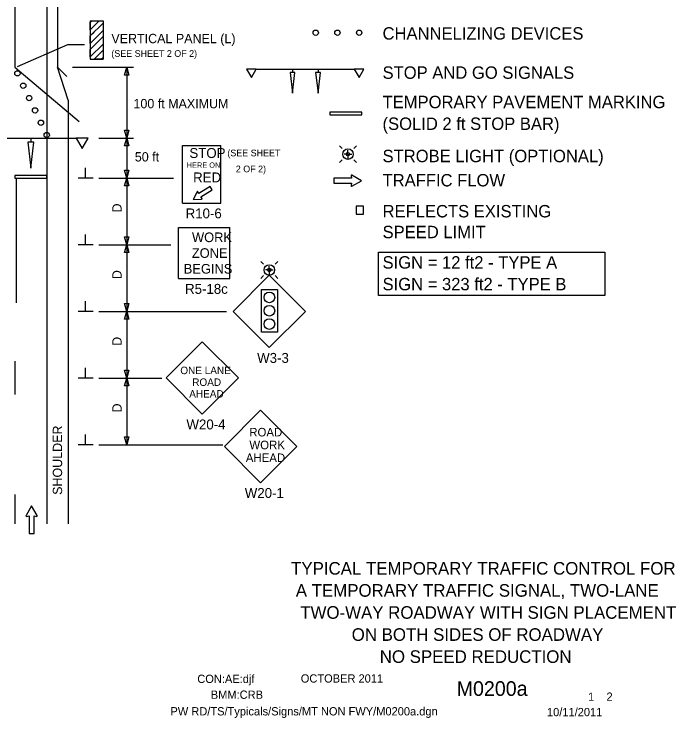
# Model space of a CAD drawing. Extents: x 16520 to 18479, y 5662 to 6927.
# Drawn here: x 16953 to 17450, y 5932 to 6460 of the extents above; entities that cross this region are included whole.
import ezdxf

# ---------------------------------------------------------------- set-up
doc = ezdxf.new("R2010")
doc.units = 0
for name, color, linetype in [('ALI_LEGAL_EX', 7, 'Continuous'), ('BORDER', 7, 'Continuous'), ('BORDER_SIGNAL_WO', 7, 'Continuous'), ('MT_SCRATCH_LEVEL_E', 7, 'Continuous'), ('PAVT_EDGE_EX', 7, 'Continuous'), ('TRAFFIC_SIGNS_PR', 7, 'Continuous'), ('TYPICAL_TEXT_DIMEN_EX', 7, 'Continuous'), ('TYPICAL_TEXT_DIMEN_PR', 7, 'Continuous')]:
    doc.layers.add(name, color=color, linetype=linetype)

msp = doc.modelspace()

# ---------------------------------------------------------------- linework, layer by layer
at = {"layer": 'ALI_LEGAL_EX'}
for points in [[(16954.78, 6336.76), (16954.78, 6243.13)], [(16953.78, 6199.43), (16953.78, 6174.43)], [(16953.78, 6099.43), (16953.78, 6077.5)]]:
    msp.add_lwpolyline(points, dxfattribs=at)
at = {"layer": 'MT_SCRATCH_LEVEL_E'}
for p, q in [((17206.32, 6336.64), (17193.07, 6336.64)), ((17193.07, 6336.64), (17193.07, 6332.9)), ((17206.32, 6336.64), (17193.07, 6336.64)), ((17193.07, 6336.64), (17193.07, 6332.9)), ((17206.01, 6338.42), (17206.32, 6336.64)), ((17206.01, 6338.42), (17206.32, 6336.64)), ((17213.93, 6334.79), (17206.69, 6338.9)), ((17213.93, 6334.79), (17206.69, 6338.9)), ((17193.07, 6332.9), (17206.32, 6332.9)), ((17193.07, 6332.9), (17206.32, 6332.9)), ((17206.32, 6332.9), (17206.01, 6331.12)), ((17206.32, 6332.9), (17206.01, 6331.12)), ((17206.69, 6330.64), (17213.93, 6334.79)), ((17206.69, 6330.64), (17213.93, 6334.79)), ((16966.37, 6090.97), (16962.26, 6083.73)), ((16966.37, 6090.97), (16962.26, 6083.73)), ((16970.52, 6083.73), (16966.37, 6090.97)), ((16970.52, 6083.73), (16966.37, 6090.97)), ((16962.74, 6083.04), (16964.52, 6083.36)), ((16962.74, 6083.04), (16964.52, 6083.36)), ((16964.52, 6083.36), (16964.52, 6070.1)), ((16964.52, 6083.36), (16964.52, 6070.1)), ((16968.26, 6070.1), (16968.26, 6083.36)), ((16968.26, 6083.36), (16970.04, 6083.04)), ((16968.26, 6070.1), (16968.26, 6083.36)), ((16968.26, 6083.36), (16970.04, 6083.04)), ((16964.52, 6070.1), (16968.26, 6070.1)), ((16964.52, 6070.1), (16968.26, 6070.1))]:
    msp.add_line(p, q, dxfattribs=at)
for centre, start, end in [((17206.47, 6338.49), 60.4248, 189.9638), ((17206.47, 6338.49), 60.4248, 189.9638), ((17206.47, 6331.05), 170.0362, 299.7731), ((17206.47, 6331.05), 170.0362, 299.7731), ((16962.67, 6083.5), 150.4248, 279.9638), ((16962.67, 6083.5), 150.4248, 279.9638), ((16970.11, 6083.5), 260.0362, 29.7731), ((16970.11, 6083.5), 260.0362, 29.7731)]:
    msp.add_arc(centre, 0.463, start, end, dxfattribs=at)
at = {"layer": 'PAVT_EDGE_EX'}
for p, q in [((16977.78, 6899.43), (16977.78, 6077.5)), ((16953.78, 6551.35), (16953.78, 6419.96)), ((16985.78, 6551.35), (16985.78, 6419.96)), ((16953.78, 6419.96), (17002.19, 6379.34)), ((16985.78, 6419.96), (16992.85, 6412.89)), ((16993.78, 6395.26), (16985.78, 6419.96)), ((16993.78, 6395.26), (16993.78, 6077.5))]:
    msp.add_line(p, q, dxfattribs=at)
at = {"layer": 'TRAFFIC_SIGNS_PR'}
for p, q in [((17010.4, 6454.77), (17020, 6454.77)), ((17010.4, 6454.77), (17010.4, 6425.97)), ((17010.4, 6453.68), (17011.49, 6454.77)), ((17010.4, 6448.02), (17017.15, 6454.77)), ((17010.4, 6454.77), (17020, 6454.77)), ((17010.4, 6454.77), (17010.4, 6425.97)), ((17010.4, 6453.68), (17011.49, 6454.77)), ((17010.4, 6448.02), (17017.15, 6454.77)), ((17010.4, 6443.5), (17020, 6453.1)), ((17010.4, 6443.5), (17020, 6453.1)), ((17020, 6454.77), (17020, 6425.97)), ((17020, 6454.77), (17020, 6425.97)), ((17010.4, 6437.84), (17020, 6447.44)), ((17010.4, 6437.84), (17020, 6447.44)), ((17010.4, 6433.32), (17020, 6442.92)), ((17010.4, 6433.32), (17020, 6442.92)), ((17011.81, 6444.91), (17013.23, 6446.33)), ((17011.81, 6444.91), (17013.23, 6446.33)), ((17010.4, 6427.66), (17020, 6437.26)), ((17010.4, 6427.66), (17020, 6437.26)), ((17013.24, 6425.97), (17020, 6432.73)), ((17013.24, 6425.97), (17020, 6432.73)), ((17010.4, 6425.97), (17020, 6425.97)), ((17010.4, 6425.97), (17020, 6425.97)), ((17018.89, 6425.97), (17020, 6427.08)), ((17018.89, 6425.97), (17020, 6427.08)), ((17134.84, 6418.4), (17208.44, 6418.4)), ((17162.04, 6418.4), (17162.04, 6415.98)), ((17181.24, 6418.4), (17181.24, 6415.98)), ((16907.78, 6366.76), (16999.78, 6366.76)), ((16965.78, 6366.76), (16965.78, 6363.74)), ((17079.55, 6361.23), (17108.35, 6361.23)), ((17079.55, 6318.03), (17079.55, 6361.23)), ((17093.95, 6361.23), (17093.95, 6361.23)), ((17108.35, 6318.03), (17108.35, 6361.23)), ((17199.4, 6359.04), (17197.37, 6361.07)), ((17203.68, 6354.76), (17203.68, 6357.63)), ((17207.96, 6359.04), (17209.99, 6361.07)), ((17203.68, 6354.76), (17200.8, 6354.76)), ((17203.68, 6354.76), (17203.68, 6350.82)), ((17203.68, 6354.76), (17206.56, 6354.76)), ((17199.4, 6350.47), (17197.37, 6348.44)), ((17209.99, 6348.44), (17207.96, 6350.47)), ((17079.55, 6318.03), (17108.35, 6318.03)), ((17076.71, 6261.4), (17076.71, 6299.8)), ((17076.71, 6299.8), (17115.11, 6299.8)), ((17115.11, 6261.4), (17115.11, 6299.8)), ((17140.42, 6272.16), (17138.39, 6274.19)), ((17148.98, 6272.16), (17151.01, 6274.19)), ((17144.7, 6267.88), (17141.82, 6267.88)), ((17144.7, 6267.88), (17144.7, 6270.76)), ((17144.7, 6267.88), (17144.7, 6263.94)), ((17144.7, 6267.88), (17147.58, 6267.88)), ((17144.7, 6263.94), (17117.55, 6236.79)), ((17140.42, 6263.6), (17138.39, 6261.56)), ((17171.85, 6236.79), (17144.7, 6263.94)), ((17151.01, 6261.56), (17148.98, 6263.6)), ((17076.71, 6261.4), (17115.11, 6261.4)), ((17117.55, 6236.79), (17144.7, 6209.63)), ((17144.7, 6209.63), (17171.85, 6236.79)), ((17094.37, 6214.01), (17067.22, 6186.86)), ((17121.52, 6186.86), (17094.37, 6214.01)), ((17067.22, 6186.86), (17094.37, 6159.71)), ((17094.37, 6159.71), (17121.52, 6186.86)), ((17138.12, 6162.62), (17110.97, 6135.46)), ((17165.27, 6135.46), (17138.12, 6162.62)), ((17110.97, 6135.46), (17138.12, 6108.31)), ((17138.12, 6108.31), (17165.27, 6135.46))]:
    msp.add_line(p, q, dxfattribs=at)
for points in [[(17011.49, 6454.77), (17017.15, 6454.77), (17010.4, 6448.02), (17010.4, 6453.68)], [(17011.49, 6454.77), (17017.15, 6454.77), (17010.4, 6448.02), (17010.4, 6453.68)], [(17010.4, 6443.5), (17020, 6453.1), (17020, 6447.44), (17010.4, 6437.84)], [(17010.4, 6443.5), (17020, 6453.1), (17020, 6447.44), (17010.4, 6437.84)], [(17010.4, 6433.32), (17020, 6442.92), (17020, 6437.26), (17010.4, 6427.66)], [(17010.4, 6433.32), (17020, 6442.92), (17020, 6437.26), (17010.4, 6427.66)], [(17020, 6432.73), (17020, 6427.08), (17018.89, 6425.97), (17013.24, 6425.97)], [(17020, 6432.73), (17020, 6427.08), (17018.89, 6425.97), (17013.24, 6425.97)], [(17127.64, 6418.4), (17131.24, 6412.16), (17134.84, 6418.4)], [(17160.24, 6415.98), (17162.04, 6400.44), (17163.84, 6415.98)], [(17179.44, 6415.98), (17181.24, 6400.44), (17183.04, 6415.98)], [(17208.44, 6418.4), (17212.04, 6412.16), (17215.64, 6418.4)], [(17190.06, 6386.37), (17190.06, 6384.37), (17214.06, 6384.37), (17214.06, 6386.37)], [(16963.53, 6363.74), (16965.78, 6344.32), (16968.03, 6363.74)], [(16999.78, 6366.76), (17004.28, 6358.97), (17008.78, 6366.76)], [(16953.78, 6338.76), (16953.78, 6336.76), (16977.78, 6336.76), (16977.78, 6338.76)], [(17209.8, 6309.67), (17215.39, 6309.67), (17215.39, 6315.84), (17209.8, 6315.84)], [(17150.76, 6221.33), (17138.76, 6221.33), (17138.76, 6253.33), (17150.76, 6253.33)]]:
    msp.add_lwpolyline(points, close=True, dxfattribs=at)
for points in [[(17090.56, 6326.48), (17087.51, 6320.84), (17093.9, 6321.09)], [(17094.15, 6321.68), (17093.23, 6322.71), (17101.89, 6328.07), (17100.38, 6330.51), (17091.72, 6325.16), (17091.21, 6326.44)]]:
    msp.add_lwpolyline(points, dxfattribs=at)
for centre, radius in [((17179.46, 6445.85), 2), ((17195.76, 6445.85), 2), ((17212.06, 6445.85), 2), ((16955.78, 6415.38), 2), ((16960.18, 6406.12), 2), ((16964.58, 6396.85), 2), ((16968.98, 6387.59), 2), ((16973.38, 6378.32), 2), ((16977.78, 6369.06), 2), ((17203.68, 6354.76), 3.94), ((17203.68, 6354.76), 1.28), ((17144.7, 6267.88), 3.94), ((17144.7, 6267.88), 1.28), ((17144.76, 6247.33), 4), ((17144.76, 6237.33), 4), ((17144.76, 6227.33), 4)]:
    msp.add_circle(centre, radius, dxfattribs=at)
for centre, radius, start, end in [((17090.88, 6326.31), 0.355, 21.7152, 151.4266), ((17093.89, 6321.44), 0.354, 272.1787, 41.9178)]:
    msp.add_arc(centre, radius, start, end, dxfattribs=at)
at = {"layer": 'TYPICAL_TEXT_DIMEN_EX'}
msp.add_lwpolyline([(17226.59, 6281.14), (17396.24, 6281.14), (17396.24, 6248.6), (17226.59, 6248.6)], close=True, dxfattribs=at)
at = {"layer": 'TYPICAL_TEXT_DIMEN_PR'}
for p, q in [((16955.78, 6420.47), (16993.57, 6436.91)), ((16955.78, 6420.47), (16993.57, 6436.91)), ((16993.57, 6436.91), (17006.03, 6436.91)), ((16993.57, 6436.91), (17006.03, 6436.91)), ((16997.08, 6419.96), (17042.78, 6419.96)), ((17036.21, 6414.1), (17037.78, 6419.96)), ((17037.78, 6419.96), (17037.78, 6366.76)), ((17037.78, 6419.96), (17039.35, 6414.1)), ((17037.78, 6414.1), (17036.21, 6414.1)), ((17039.35, 6414.1), (17037.78, 6414.1)), ((17037.78, 6366.76), (17036.21, 6372.63)), ((17036.21, 6372.63), (17037.78, 6372.63)), ((17037.78, 6372.63), (17039.35, 6372.63)), ((17039.35, 6372.63), (17037.78, 6366.76)), ((17016.78, 6366.76), (17042.78, 6366.76)), ((17036.21, 6360.9), (17037.78, 6366.76)), ((17037.78, 6366.76), (17039.35, 6360.9)), ((17037.78, 6366.76), (17037.78, 6336.76)), ((17037.78, 6360.9), (17036.21, 6360.9)), ((17039.35, 6360.9), (17037.78, 6360.9)), ((17006.91, 6336.76), (17006.91, 6344.55)), ((17037.78, 6336.76), (17036.21, 6342.63)), ((17036.21, 6342.63), (17037.78, 6342.63)), ((17037.78, 6342.63), (17039.35, 6342.63)), ((17039.35, 6342.63), (17037.78, 6336.76)), ((17012.53, 6336.76), (17001.28, 6336.76)), ((17016.78, 6336.76), (17072.75, 6336.76)), ((17036.21, 6330.9), (17037.78, 6336.76)), ((17037.78, 6336.76), (17037.78, 6286.76)), ((17037.78, 6336.76), (17039.35, 6330.9)), ((17037.78, 6330.9), (17036.21, 6330.9)), ((17039.35, 6330.9), (17037.78, 6330.9)), ((17006.91, 6286.76), (17006.91, 6294.55)), ((17037.78, 6286.76), (17036.21, 6292.63)), ((17036.21, 6292.63), (17037.78, 6292.63)), ((17037.78, 6292.63), (17039.35, 6292.63)), ((17039.35, 6292.63), (17037.78, 6286.76)), ((17012.53, 6286.76), (17001.28, 6286.76)), ((17016.78, 6286.76), (17070.8, 6286.76)), ((17036.21, 6280.9), (17037.78, 6286.76)), ((17036.21, 6280.9), (17037.78, 6286.76)), ((17037.78, 6286.76), (17037.78, 6236.76)), ((17037.78, 6286.76), (17039.35, 6280.9)), ((17037.78, 6286.76), (17039.35, 6280.9)), ((17037.78, 6280.9), (17036.21, 6280.9)), ((17037.78, 6280.9), (17036.21, 6280.9)), ((17039.35, 6280.9), (17037.78, 6280.9)), ((17039.35, 6280.9), (17037.78, 6280.9)), ((17006.91, 6236.76), (17006.91, 6244.55)), ((17037.78, 6236.76), (17036.21, 6242.63)), ((17036.21, 6242.63), (17037.78, 6242.63)), ((17037.78, 6236.76), (17036.21, 6242.63)), ((17036.21, 6242.63), (17037.78, 6242.63)), ((17037.78, 6242.63), (17039.35, 6242.63)), ((17039.35, 6242.63), (17037.78, 6236.76)), ((17037.78, 6242.63), (17039.35, 6242.63)), ((17039.35, 6242.63), (17037.78, 6236.76)), ((17012.53, 6236.76), (17001.28, 6236.76)), ((17016.78, 6236.76), (17112.49, 6236.76)), ((17036.21, 6230.9), (17037.78, 6236.76)), ((17036.21, 6230.9), (17037.78, 6236.76)), ((17037.78, 6236.76), (17037.78, 6186.76)), ((17037.78, 6236.76), (17039.35, 6230.9)), ((17037.78, 6236.76), (17039.35, 6230.9)), ((17037.78, 6230.9), (17036.21, 6230.9)), ((17037.78, 6230.9), (17036.21, 6230.9)), ((17039.35, 6230.9), (17037.78, 6230.9)), ((17039.35, 6230.9), (17037.78, 6230.9)), ((17006.91, 6186.76), (17006.91, 6194.55)), ((17037.78, 6186.76), (17036.21, 6192.63)), ((17036.21, 6192.63), (17037.78, 6192.63)), ((17037.78, 6192.63), (17039.35, 6192.63)), ((17039.35, 6192.63), (17037.78, 6186.76)), ((17012.53, 6186.76), (17001.28, 6186.76)), ((17016.78, 6186.76), (17064.09, 6186.76)), ((17036.21, 6180.9), (17037.78, 6186.76)), ((17037.78, 6186.76), (17037.78, 6136.76)), ((17037.78, 6186.76), (17039.35, 6180.9)), ((17037.78, 6180.9), (17036.21, 6180.9)), ((17039.35, 6180.9), (17037.78, 6180.9)), ((17006.91, 6136.76), (17006.91, 6144.55)), ((17037.78, 6136.76), (17036.21, 6142.63)), ((17036.21, 6142.63), (17037.78, 6142.63)), ((17037.78, 6142.63), (17039.35, 6142.63)), ((17039.35, 6142.63), (17037.78, 6136.76)), ((17012.53, 6136.76), (17001.28, 6136.76)), ((17016.78, 6136.76), (17109.88, 6136.76))]:
    msp.add_line(p, q, dxfattribs=at)

# ---------------------------------------------------------------- texts
at = {"layer": 'BORDER'}
for s, p in [('TYPICAL TEMPORARY TRAFFIC CONTROL FOR', (17161.04, 6039.32)), ('A TEMPORARY TRAFFIC SIGNAL, TWO-LANE', (17164.56, 6022.77)), ('TWO-WAY ROADWAY WITH SIGN PLACEMENT', (17167.92, 6006.22)), ('ON BOTH SIDES OF ROADWAY', (17206.49, 5989.66)), ('NO SPEED REDUCTION', (17227.54, 5973.11))]:
    msp.add_text(s, height=9.4427, dxfattribs=at).set_placement(p)
at = {"layer": 'BORDER_SIGNAL_WO'}
for s, height, p in [('CON:AE:djf', 6.2, (17090.69, 5958.06)), ('    OCTOBER 2011    ', 6.2, (17159.08, 5958.34)), ('    M0200a    ', 11, (17268.86, 5948.38)), ('BMM:CRB   ', 6.2, (17100.81, 5946.17)), (' 1    2 ', 6.2, (17381.45, 5944.7)), ('PW RD/TS/Typicals/Signs/MT NON FWY/M0200a.dgn     ', 6.2, (17070.55, 5933.71)), ('10/11/2011    ', 6.2, (17352.93, 5933.13))]:
    msp.add_text(s, height=height, dxfattribs=at).set_placement(p)
at = {"layer": 'TRAFFIC_SIGNS_PR'}
for s, height, p in [('STOP', 7.44, (17084.76, 6351.89)), ('HERE ON', 4, (17082.76, 6344.53)), ('RED', 7.44, (17087.56, 6333.58)), ('R10-6', 7.44, (17081.94, 6306.59)), ('WORK', 7.217, (17086.71, 6288.77)), ('ZONE', 7.217, (17086.59, 6276.95)), ('BEGINS', 7.217, (17080.52, 6265.15)), ('R5-18c', 7.44, (17081.52, 6249.96)), ('W3-3', 7.44, (17135.57, 6198.19)), ('ONE LANE', 5.6, (17077.95, 6189.73)), ('ROAD', 5.6, (17086.9, 6180.93)), ('AHEAD', 5.6, (17084.66, 6172.13)), ('W20-4', 7.44, (17082.55, 6148.27)), ('ROAD', 6.4, (17129.66, 6143)), ('WORK', 6.4, (17129.77, 6133.4)), ('AHEAD', 6.4, (17127.08, 6123.8)), ('W20-1', 7.44, (17126.29, 6096.87))]:
    msp.add_text(s, height=height, dxfattribs=at).set_placement(p)
at = {"layer": 'TYPICAL_TEXT_DIMEN_EX'}
for s, p in [('CHANNELIZING DEVICES', (17229.62, 6440.68)), ('STOP AND GO SIGNALS', (17229.62, 6411.28)), ('TEMPORARY PAVEMENT MARKING', (17229.62, 6389.23)), ('(SOLID 2 ft STOP BAR)', (17229.62, 6372.93)), ('STROBE LIGHT (OPTIONAL)', (17229.62, 6348.73)), ('TRAFFIC FLOW', (17229.62, 6330.55)), ('REFLECTS EXISTING', (17229.63, 6307.31)), ('SPEED LIMIT', (17229.63, 6291.71)), ('SIGN = 12 ft2 - TYPE A', (17229.62, 6268.91)), ('SIGN = 323 ft2 - TYPE B', (17229.62, 6252.61))]:
    msp.add_text(s, height=9.3, dxfattribs=at).set_placement(p)
at = {"layer": 'TYPICAL_TEXT_DIMEN_PR'}
for s, height, p in [('VERTICAL PANEL (L)', 7, (17026.25, 6438)), ('VERTICAL PANEL (L)', 7, (17026.25, 6438)), ('(SEE SHEET 2 OF 2)', 5, (17026.25, 6427.75)), ('(SEE SHEET 2 OF 2)', 5, (17026.25, 6427.75)), ('100 ft MAXIMUM', 7, (17042.82, 6389.17)), ('(SEE SHEET', 5, (17113.25, 6353.17)), ('50 ft', 7, (17043.85, 6349.25)), ('2 OF 2)', 5, (17119.58, 6341.17))]:
    msp.add_text(s, height=height, dxfattribs=at).set_placement(p)
for s, p in [('D', (17033.94, 6310.98)), ('D', (17033.94, 6260.98)), ('D', (17033.94, 6260.98)), ('D', (17033.94, 6210.98)), ('D', (17033.94, 6160.98)), ('SHOULDER', (16989.31, 6099.18))]:
    msp.add_text(s, height=7, rotation=90, dxfattribs=at).set_placement(p)

doc.saveas('drawing.dxf')
